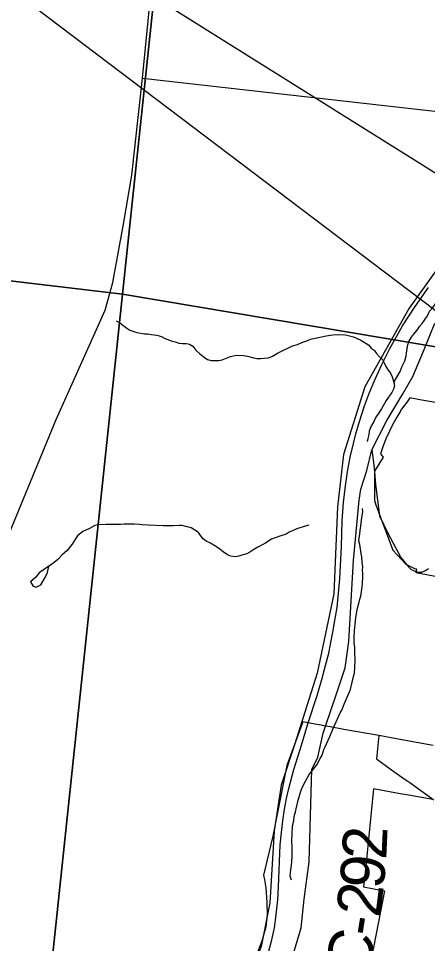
# Model space of a CAD drawing. Extents: x 0 to 34, y -3.9 to 26.2.
# Drawn here: x 6.675 to 7.199, y 15.083 to 16.268 of the extents above; entities that cross this region are included whole.
import ezdxf

# ---------------------------------------------------------------- set-up
doc = ezdxf.new("R2010")
doc.units = 0
for name, color, linetype in [('GM_X_City_Street', 7, 'Continuous'), ('GM_X_Corporation', 7, 'Continuous'), ('GM_X_County_Road', 7, 'Continuous'), ('GM_X_County_Road_Text', 7, 'Continuous'), ('GM_X_Interchange_Ramps', 7, 'Continuous'), ('GM_X_Minor_Lake', 7, 'Continuous'), ('GM_X_Minor_River', 7, 'Continuous'), ('GM_X_Rail_Line', 7, 'Continuous'), ('GM_X_Section', 7, 'Continuous'), ('SH_Text', 7, 'Continuous')]:
    doc.layers.add(name, color=color, linetype=linetype)

msp = doc.modelspace()

# ---------------------------------------------------------------- linework, layer by layer
at = {"layer": 'GM_X_City_Street'}
msp.add_lwpolyline([(7.1277, 15.7156), (7.1308, 15.6924), (7.1323, 15.6711), (7.1376, 15.6307), (7.1481, 15.6085), (7.165, 15.5777), (7.1746, 15.5657), (7.1781, 15.5623), (7.1821, 15.5602), (7.1872, 15.5589), (7.1916, 15.5589), (7.1965, 15.5609), (7.2004, 15.5636)], dxfattribs=at)
at = {"layer": 'GM_X_Corporation'}
for points in [[(7.2291, 15.7727), (7.1893, 15.7797), (7.1762, 15.782), (7.1729, 15.7772), (7.1683, 15.7709), (7.1661, 15.7682), (7.1654, 15.7672), (7.1647, 15.7661), (7.1596, 15.7574), (7.1547, 15.7485), (7.1502, 15.7395), (7.1462, 15.7305), (7.1422, 15.7205), (7.1386, 15.7105), (7.1401, 15.7087), (7.1422, 15.7061), (7.131, 15.6883), (7.1313, 15.6506), (7.1329, 15.6451), (7.1545, 15.587), (7.1712, 15.569), (7.1822, 15.5636), (7.1851, 15.5631), (7.1843, 15.5583), (7.2638, 15.5433)], [(7.2063, 15.3367), (7.1754, 15.3422), (7.1593, 15.3451), (7.1367, 15.3493), (7.1367, 15.3492), (7.092, 15.3572), (7.0742, 15.3604), (7.0685, 15.3614), (7.0626, 15.3625), (7.0546, 15.3639), (7.0392, 15.3667), (7.0189, 15.3107), (7.0063, 15.2485), (7.0006, 15.2204), (6.9887, 15.1705), (6.99, 15.1643), (6.9917, 15.154), (6.9932, 15.1351), (6.9933, 15.1193), (6.9916, 15.1039), (6.9866, 15.0855), (6.9802, 15.0689)]]:
    msp.add_lwpolyline(points, dxfattribs=at)
at = {"layer": 'GM_X_County_Road'}
for points in [[(6.5955, 15.4411), (6.651, 15.5802), (6.723, 15.7542), (6.786, 15.8947), (6.7893, 15.9071), (6.7958, 15.9302), (6.8094, 16.0047), (6.8201, 16.0676), (6.8335, 16.192), (6.8484, 16.3393), (6.8718, 16.5287), (6.9167, 16.9179)], [(6.8335, 16.192), (7.2539, 16.1444), (7.2563, 16.1451), (7.2585, 16.1466), (7.2604, 16.1491), (7.2617, 16.1522), (7.2656, 16.1814), (7.2666, 16.1841), (7.2687, 16.1867), (7.2706, 16.1885), (7.2716, 16.189), (7.273, 16.1893), (7.4427, 16.1658), (7.4616, 16.1624), (7.4718, 16.158), (7.478, 16.1458), (7.568, 16.1225), (7.7154, 16.1013), (7.7866, 16.0916), (7.7895, 16.0855), (7.794, 16.0794), (7.7973, 16.0771), (7.8001, 16.0756), (7.8064, 16.0731)], [(7.0788, 15.3923), (7.0935, 15.4359), (7.098, 15.4697), (7.1041, 15.5736), (7.1113, 15.651), (7.1138, 15.665), (7.1211, 15.6891), (7.1277, 15.7156), (7.147, 15.7532), (7.1674, 15.7874), (7.1804, 15.8095), (7.1939, 15.8419), (7.2086, 15.8777)], [(6.927, 14.8765), (6.9463, 14.9081), (6.9851, 14.97), (6.9953, 14.9881), (7.0071, 15.0102), (7.0181, 15.0457), (7.0273, 15.0699), (7.037, 15.1027), (7.0411, 15.1395), (7.0474, 15.1876), (7.0508, 15.3057), (7.0583, 15.3215), (7.0653, 15.3525), (7.0781, 15.3904), (7.0788, 15.3923)]]:
    msp.add_lwpolyline(points, dxfattribs=at)
at = {"layer": 'GM_X_Interchange_Ramps'}
for points in [[(7.2291, 15.7727), (7.1893, 15.7797), (7.1762, 15.782), (7.1729, 15.7772), (7.1683, 15.7709), (7.1661, 15.7682), (7.1654, 15.7672), (7.1647, 15.7661), (7.1596, 15.7574), (7.1547, 15.7485), (7.1502, 15.7395), (7.1462, 15.7305), (7.1422, 15.7205), (7.1386, 15.7105), (7.1401, 15.7087), (7.1422, 15.7061), (7.131, 15.6883), (7.1313, 15.6506), (7.1329, 15.6451), (7.1545, 15.587), (7.1712, 15.569), (7.1822, 15.5636), (7.1851, 15.5631), (7.1843, 15.5583), (7.2638, 15.5433)], [(7.2063, 15.3367), (7.1754, 15.3422), (7.1593, 15.3451), (7.1367, 15.3493), (7.1337, 15.3193), (7.1531, 15.3054), (7.1705, 15.2931), (7.1738, 15.2907), (7.1764, 15.2889), (7.1933, 15.2768), (7.2072, 15.2669)], [(7.206, 15.2671), (7.1746, 15.2728), (7.1641, 15.2746), (7.1502, 15.2772), (7.1298, 15.2809), (7.1251, 15.2337), (7.1198, 15.1819), (7.1172, 15.1552), (7.1301, 15.1528), (7.144, 15.1504), (7.1363, 15.1105), (7.1295, 15.0753)]]:
    msp.add_lwpolyline(points, dxfattribs=at)
at = {"layer": 'GM_X_Minor_Lake'}
for points in [[(6.7136, 15.5663), (6.7014, 15.558), (6.6971, 15.5524), (6.6901, 15.5465), (6.6934, 15.5407), (6.6972, 15.5395), (6.7033, 15.5424), (6.7088, 15.5518), (6.712, 15.5582)], [(6.712, 15.5582), (6.7136, 15.5663)]]:
    msp.add_lwpolyline(points, dxfattribs=at)
at = {"layer": 'GM_X_Minor_River'}
for points in [[(7.1563, 15.8004), (7.1569, 15.8037), (7.1597, 15.8085), (7.1642, 15.8159), (7.1667, 15.8227), (7.17, 15.8294), (7.1718, 15.8358), (7.172, 15.8395), (7.1729, 15.8456), (7.1739, 15.8501), (7.1752, 15.8542), (7.1784, 15.8598), (7.1809, 15.8635), (7.1856, 15.869), (7.1889, 15.8734), (7.1921, 15.8775), (7.1953, 15.8819), (7.1989, 15.8871), (7.2018, 15.8934), (7.2058, 15.8978), (7.2094, 15.9026), (7.2133, 15.9062), (7.2181, 15.9121), (7.2255, 15.9252)], [(6.8, 15.8808), (6.8045, 15.8784), (6.8085, 15.8752), (6.8137, 15.8715), (6.8174, 15.8691), (6.8227, 15.867), (6.8264, 15.8657), (6.8362, 15.8641), (6.8404, 15.864), (6.8453, 15.8634), (6.8521, 15.8623), (6.8581, 15.8606), (6.8618, 15.8585), (6.8671, 15.8564), (6.8716, 15.8547), (6.8757, 15.8538), (6.8802, 15.8524), (6.8851, 15.8518), (6.8901, 15.8516), (6.8939, 15.8511), (6.8983, 15.8483), (6.9019, 15.8432), (6.907, 15.8384), (6.9126, 15.8344), (6.917, 15.8315), (6.9219, 15.8298), (6.9314, 15.8298), (6.936, 15.8307), (6.9399, 15.8325), (6.9464, 15.8352), (6.9541, 15.8368), (6.9632, 15.8364), (6.9681, 15.8355), (6.9749, 15.8337), (6.9802, 15.8327), (6.9855, 15.8325), (6.99, 15.833), (6.995, 15.8336), (7.0004, 15.8357), (7.0066, 15.8392), (7.0117, 15.842), (7.021, 15.8462), (7.026, 15.8487), (7.0325, 15.8507), (7.038, 15.8531), (7.0445, 15.8551), (7.0491, 15.8572), (7.0595, 15.8594), (7.0633, 15.8604), (7.0691, 15.8617), (7.0775, 15.8629), (7.0832, 15.8634), (7.0938, 15.8629), (7.1044, 15.8602), (7.1137, 15.856), (7.1233, 15.8499), (7.127, 15.846), (7.1307, 15.8432), (7.1335, 15.8389), (7.1376, 15.8349), (7.1412, 15.8313), (7.1433, 15.8271), (7.1458, 15.8224), (7.1487, 15.8177), (7.1516, 15.8138), (7.1537, 15.8091), (7.156, 15.8022), (7.1566, 15.7976), (7.1553, 15.7931), (7.1532, 15.789), (7.146, 15.7787), (7.1423, 15.772), (7.1399, 15.7679), (7.1366, 15.7631), (7.133, 15.7575), (7.1297, 15.7508), (7.1273, 15.7468), (7.1256, 15.743), (7.1243, 15.7393), (7.1238, 15.7351), (7.1224, 15.7299), (7.1219, 15.7261)], [(7.0245, 15.1638), (7.0232, 15.1691), (7.0234, 15.1733), (7.0239, 15.1771), (7.0245, 15.1828), (7.0251, 15.1877), (7.0257, 15.1941), (7.0254, 15.2048), (7.025, 15.2151), (7.0257, 15.2223), (7.0261, 15.2336), (7.0275, 15.24), (7.0281, 15.2453), (7.0299, 15.2517), (7.0327, 15.2649), (7.0344, 15.2706), (7.037, 15.2792), (7.0396, 15.2852), (7.0428, 15.2907), (7.0473, 15.2993), (7.0541, 15.3077), (7.0573, 15.3118), (7.0615, 15.32), (7.0639, 15.3241), (7.0661, 15.3312), (7.0677, 15.3349), (7.0715, 15.3435), (7.074, 15.348), (7.0777, 15.3573), (7.0819, 15.3667), (7.0869, 15.3782), (7.0894, 15.3819), (7.0932, 15.3917), (7.0978, 15.4025), (7.1003, 15.4085), (7.1012, 15.4122), (7.103, 15.4194), (7.1044, 15.425), (7.1053, 15.4292), (7.1059, 15.4364), (7.1063, 15.4458), (7.1059, 15.4557), (7.1058, 15.4626), (7.1052, 15.4672), (7.1052, 15.4744), (7.1055, 15.4839), (7.1068, 15.496), (7.1073, 15.5005), (7.1088, 15.5104), (7.1098, 15.5141), (7.1111, 15.5186), (7.1124, 15.5243), (7.1137, 15.528), (7.1153, 15.5401), (7.1159, 15.5443), (7.1162, 15.553), (7.116, 15.5576), (7.1158, 15.5614), (7.116, 15.5656), (7.1154, 15.5709), (7.115, 15.5785), (7.114, 15.5827), (7.1125, 15.5942), (7.1112, 15.5988), (7.1113, 15.6026), (7.1123, 15.6075), (7.1128, 15.6121), (7.1138, 15.6177), (7.114, 15.6215), (7.1145, 15.6253), (7.1155, 15.6313), (7.1161, 15.6359), (7.1159, 15.6404)], [(7.047, 15.619), (7.0424, 15.6176), (7.0316, 15.6143), (7.0219, 15.6101), (7.0177, 15.6073), (7.0111, 15.6053), (7.0038, 15.6025), (6.9992, 15.6012), (6.9906, 15.5955), (6.9817, 15.5909), (6.9751, 15.587), (6.9712, 15.5845), (6.9673, 15.5824), (6.9611, 15.5804), (6.9573, 15.5794), (6.9531, 15.5784), (6.947, 15.5794), (6.9425, 15.5811), (6.9373, 15.5848), (6.9311, 15.5896), (6.9262, 15.5924), (6.9207, 15.5957), (6.9155, 15.5986), (6.9114, 15.6014), (6.9082, 15.6057), (6.9053, 15.6097), (6.896, 15.6154), (6.8911, 15.6167), (6.8847, 15.6185), (6.8805, 15.6187), (6.8729, 15.6182), (6.8638, 15.6182), (6.86, 15.618), (6.841, 15.6188), (6.8334, 15.6195), (6.8297, 15.6196), (6.8232, 15.6203), (6.8183, 15.6201), (6.8103, 15.6201), (6.8057, 15.6199), (6.7985, 15.6198), (6.7871, 15.6199), (6.7764, 15.6192), (6.7726, 15.6186), (6.7656, 15.6147), (6.7571, 15.6109), (6.7504, 15.6051), (6.7476, 15.6014), (6.7435, 15.5947), (6.7372, 15.5866), (6.7301, 15.5804), (6.7253, 15.5749), (6.7182, 15.5695), (6.7136, 15.5663)]]:
    msp.add_lwpolyline(points, dxfattribs=at)
at = {"layer": 'GM_X_Rail_Line'}
for points in [[(7.5395, 16.2809), (7.4908, 16.2066), (7.4431, 16.1532), (7.3582, 16.0883), (7.3004, 16.0403), (7.2654, 16.0107), (7.2206, 15.9597), (7.1754, 15.897), (7.1187, 15.7961), (7.0913, 15.7095), (7.0835, 15.6423), (7.0788, 15.531), (7.0578, 15.4294), (7.0284, 15.3374), (7.0116, 15.2855), (7.0026, 15.2273), (6.9969, 15.1347), (6.9859, 15.0789), (6.9627, 15.0215), (6.9209, 14.9514), (6.8813, 14.9193), (6.8289, 14.9054), (6.7886, 14.9093), (6.249, 14.9675)], [(6.9955, 15.0729), (6.9995, 15.0873), (7.0029, 15.1026), (7.0052, 15.1196), (7.0071, 15.1386), (7.008, 15.1552), (7.0103, 15.2091), (7.0118, 15.2252), (7.0134, 15.2398), (7.0156, 15.255), (7.0181, 15.2684), (7.0213, 15.2812), (7.0278, 15.3059), (7.0327, 15.3218), (7.0375, 15.3371), (7.0458, 15.3642), (7.0574, 15.4004), (7.0637, 15.421), (7.0684, 15.4392), (7.0724, 15.4548), (7.0752, 15.4686), (7.0777, 15.4816), (7.0804, 15.4967), (7.0831, 15.5132), (7.0851, 15.5317), (7.0868, 15.5502), (7.0887, 15.5916), (7.0898, 15.6245), (7.0914, 15.6481), (7.0938, 15.6695), (7.0966, 15.6873), (7.0999, 15.706), (7.104, 15.7237), (7.1072, 15.736), (7.112, 15.7517), (7.1185, 15.7719), (7.1248, 15.7888), (7.1321, 15.8059), (7.1406, 15.825), (7.1504, 15.8446), (7.1672, 15.8744), (7.1834, 15.8992), (7.2002, 15.9236)]]:
    msp.add_lwpolyline(points, dxfattribs=at)
at = {"layer": 'GM_X_Section'}
for points in [[(5.8743, 17.0495), (6.9147, 16.9222), (6.8082, 15.9151), (5.7775, 16.0372)], [(6.9147, 16.9222), (7.8864, 16.832), (7.7738, 15.7526), (6.8082, 15.9151)], [(5.7775, 16.0372), (6.8082, 15.9151), (6.7022, 14.9121), (5.6843, 15.0302)], [(7.7738, 15.7526), (7.6773, 14.7406), (6.7022, 14.9121), (6.8082, 15.9151)]]:
    msp.add_lwpolyline(points, close=True, dxfattribs=at)
at = {"layer": 'SH_Text'}
msp.add_lwpolyline([(9.6066, 14.5701), (9.6066, 14.0797), (5.8602, 16.9149)], close=True, dxfattribs=at)

# ---------------------------------------------------------------- texts
at = {"layer": 'GM_X_County_Road_Text'}
for s, rotation, p in [('2', 87.4137, (7.1461, 15.1895)), ('9', 84.5168, (7.1425, 15.1515)), ('2', 82.7575, (7.1379, 15.1149)), ('-', 81.0284, (7.134, 15.09)), ('C', 75.2481, (7.1208, 15.0387))]:
    msp.add_text(s, height=0.0568, rotation=rotation, dxfattribs=at).set_placement(p)

doc.saveas('drawing.dxf')
